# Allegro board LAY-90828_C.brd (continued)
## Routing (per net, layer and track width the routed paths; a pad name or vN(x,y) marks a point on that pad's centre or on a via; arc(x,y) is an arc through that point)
AGND: length 8.9
  TOP w0.203: U1.R6 v2(62.66,24.5)
  BOTTOM w0.381: C109.2 62.31,21.41 62.44,21.54 C31.2 ; C31.2 C29.2 61.29,22.18 61.04,22.43 60.15,22.43 C9.2 ; C31.2 62.82,22.18 63.07,22.43 63.07,24.09 v2(62.66,24.5)
  BOTTOM w0.508: C109.2 R64.2
GND: length 400.2
  TOP w0.102: U1.T16 66.63,23.44 v2(66.63,23.19) ; U1.H5 v2(61.69,27.5) U1.J4 ; U1.J10 v2(63.69,27.5) ; v2(63.69,27.5) U1.J8 ; v2(63.69,27.5) U1.K9 ; v2(63.69,27.5) U1.H9 ; U1.D9 v2(63.18,30) ; v2(99.76,34.1) 99.62,33.97 U6.B2 ; 58.86,28.5 U1.G2 ; U1.J14 66.19,27.97 v2(66.16,28) U1.H13 ; U1.E5 v2(61.69,30.01) 61.7,30 U1.D6 ; U1.P16 67.99,24.2 v2(68.13,24.2) ; U1.P12 65.68,25 v2(65.69,24.99) ; U1.P14 65.7,25 v2(65.69,24.99) ; U1.E13 v2(65.69,30) 65.61,30 65.6,30 U1.D12 ; v2(65.69,24.99) U1.N13 ; U1.P9 v2(63.18,25) ; U6.B10 100.84,31.12 v2(101.03,30.93)
  TOP w0.127: v1(56.32,27.89) 56.96,27.89 57.58,28.5 58.86,28.5 ; v2(27.18,27.31) 27.28,27.31 U8.B9
  TOP w0.203: U1.P6 U1.P7 v2(63.18,25) ; v2(28,24.32) 28,24.59 U8.B13 ; v2(23.11,26.29) 22.71,25.89 U8.M11 U8.M12 U8.N12 22.07,25.38 v2(21.53,24.83) ; U8.B1 27.71,31.14 v2(28,31.44) ; U8.B5 v2(27.21,28.88) ; U8.J13 24.21,24.44 v2(24.32,24.32) ; U41.10 14.74,17.39 v1(14.54,17.59) ; U8.N5 v2(21.54,28.88)
  TOP w0.254: v1(38.34,12.19) 38.34,12.04 38.09,11.79 U4.D3 ; v1(38.34,12.19) U4.C3 ; v1(38.34,12.19) 38.34,12.33 38.09,12.59 U4.B3 ; v2(24.45,31.44) 24.71,31.18 U8.H1 U8.H2 ; v1(21.78,31.31) U8.N1 ; U10.10 86.04,30.26 85.79,30 v1(85.79,29.66)
  TOP w0.381: R185.2 46.67,19.37 v1(46.29,18.99) ; R297.3 v1(9.71,15.31) ; C82.2 v1(10.35,40.71) ; C79.2 v1(20.76,32.19) ; U9.7 v1(9.33,34.74) ; C88.2 v1(107.12,10.23) ; Y3.2 52.68,28.48 v1(52.39,28.77) ; C67.2 v1(32.7,28.26) ; R94.2 38.52,12.01 v1(38.34,12.19) ; R197.1 84.01,29.69 v1(84.53,29.16) ; R111.1 v1(85.15,12.01) ; C46.2 v1(73.47,14.16) ; C53.2 v1(101.36,25.72) 102.04,25.72 102.37,26.05 C50.2 ; R126.2 v1(18.99,35.25) ; v1(98.87,22.04) 98.61,22.04 98.21,21.64 U7.6 ; R91.2 37.65,10.61 v1(37.91,10.86) ; v1(94.93,20.64) U7.8 ; C103.2 C102.2 54.67,19.37 54.29,19.75 v1(54.29,19.88) 53.98,20.19 U11.2 ; C150.2 v1(15.05,12.01) ; R191.2 91.88,31.94 92.28,31.55 v1(92.28,31.07) ; R134.2 v1(24.45,21.02) ; v1(65.1,16.59) 64.71,16.19 R100.1 ; C95.2 67.75,21.79 v1(68.26,22.29) 68.64,21.91 C94.2 ; D9.A v1(11.75,3.75) ; C36.2 v1(11.11,23.69) ; v1(103.57,33.34) 103.31,33.6 C42.2 ; C81.2 v1(32.7,33.85) ; v1(19.24,29.92) C78.2 ; C87.2 v1(6.68,45.72) ; R214.2 v1(10.1,37.91) ; v1(95.95,18.23) 95.95,18.36 96.48,18.89 U7.7 ; R132.2 v1(23.18,21.02) ; v1(45.27,21.91) C108.2 C104.1 ; C47.2 v1(95.95,26.36) ; D11.2 13.52,13.15 v1(13.78,12.89) ; C86.2 v1(6.68,46.87) ; C90.2 v1(105.85,44.52) ; R136.2 17.84,28.77 v1(17.72,28.64) R122.2 ; C97.2 v1(56.32,27.89) ; C45.2 v1(95.06,30.09) ; U5.7 v1(9.08,20.13) ; C43.2 v1(103.57,30.67) ; C30.2 C28.2 75.37,26.86 v1(75.63,26.61) ; Y3.4 54.64,30.16 C96.2 56.08,30.16 v1(56.32,29.91) ; C6.2 v1(16.57,35.25) ; v1(97.6,23.05) 97.6,22.67 97.32,22.39 U7.5 ; C44.2 v1(102.81,28.26) ; v1(16.57,11.62) C105.2 ; R130.2 v1(32.69,27.25) ; D14.3 v1(15.81,11.75) ; C49.2 v1(101.54,37.28) ; C58.1 v1(103.57,32.58) ; v1(100.52,37.28) C51.2 C55.2 ; C48.2 v1(103.57,31.69) ; R150.2 v1(10.48,9.47) ; v1(17.72,27.75) C80.2 ; C154.2 v1(12.64,19.88) ; v1(66.99,16.2) 67.12,16.07 R113.2 C54.2 ; C40.2 v1(10.86,24.58) ; C69.2 v1(21.65,39.95) ; v1(86.04,8.58) 85.79,8.32 R112.1 ; C85.2 v1(7.3,12.26) ; R213.2 v1(10.24,33.6) ; C60.2 v1(84.14,6.8) ; R93.2 v1(12.13,23.69) ; R135.2 v1(32.7,31.56) ; C65.2 v1(32.7,23.31) ; C101.2 v1(47.05,22.93) ; C68.2 v1(32.7,30.55) ; C73.2 v1(17.72,26.23) ; R133.2 v1(32.7,29.28) ; R149.2 v1(3.87,15.18) ; D10.A v1(11.75,5.27) ; C59.2 v1(84.14,12.01)
  TOP w0.508: D3.C v1(55.69,13.4) ; C34.2 v1(77.66,22.04) ; C114.2 v1(92.28,20.91) ; 39.96,43.77 v1(37.92,43.77) ; SW3.2 v1(109.7,2.01) ; C5.2 v1(16.19,37.91) ; 46.67,12.13 v1(46.67,12.13) ; 46.67,12.13 C2.2 ; 46.67,12.13 v1(46.67,12.13) ; 46.67,12.13 C3.2 ; v1(46.67,12.13) U2.2 ; C99.2 v1(88.58,27.12) ; C77.2 v1(22.03,19.24) ; C8.2 102.93,17.97 v1(103.5,17.4) U3.1 ; U11.9 v1(51.75,18.74) ; v1(10.75,48.74) SW1.2 ; R137.2 v1(24.07,35.37) ; C74.2 v1(13.14,23.18) ; C38.2 32.57,12.39 v1(32.57,13.4) C39.2 ; Y1.4 19.03,32.79 v1(19.24,32.58) ; C7.2 v1(101.54,12.64) ; R176.1 v1(91.5,28.39) ; C110.2 v1(28.26,8.83) ; Q1.1 v1(33.59,14.78) ; R122.2 16.95,29.28 16.53,29.7 Y1.2 ; C111.2 v1(29.78,8.83) ; C76.2 v1(21.02,23.69) ; v1(25.08,35.37) C70.2 ; C71.2 v1(26.35,36.14) ; C62.2 v1(93.03,23.56) ; v1(109.81,48.74) SW2.2 ; U12.4 v1(85.17,22.32) ; R86.2 v1(79.06,21.4) ; C64.2 v1(35.88,29.02) C63.2 ; v1(19.49,33.98) 20,33.47 C66.2 ; C32.2 v1(70.17,21.02) ; C107.2 v1(94.68,26.99) ; v1(13.14,24.71) C72.2 ; C1.2 v1(49.21,11.5) ; C75.2 v1(20.51,19.24) ; C83.2 v1(22.8,35.37) ; C113.2 v1(23.18,8.83) ; v1(109.81,6.16) SW3.1 ; C98.2 v1(87.57,27.12) ; SW2.1 v1(109.8,52.89) ; C41.2 v1(33.08,8.58) ; SW1.1 v1(10.87,52.89) ; C115.2 v1(92.79,44.53) ; R204.1 v1(93.79,17.85) ; C106.2 v1(94.68,25.98) ; C4.2 v1(49.21,12.77) ; C112.2 v1(26.73,8.83)
  TOP w0.762: J10.SH2 J10.SH4 J10.SH3 J10.SH1 ; J11.SH1 J11.SH3 J11.SH4 J11.SH2
  GND w0.381: 6.05,33.07 J10.A12 ; J10.A12 5.46,33.67 ; J10.A12 6.65,33.67 ; 1.69,25.14 J11.SH3 ; J11.SH3 1.69,26.57 ; J11.SH3 2.81,25.86 ; J7.9 89.29,6.16 ; J7.9 88.2,7.26 ; J7.9 87.11,6.16 ; J7.9 88.2,5.07 ; 29.53,40.07 JP5.1 ; JP5.1 28.38,41.22 ; JP5.1 29.53,42.36 ; JP5.1 30.67,41.22 ; J7.10 89.29,3.62 ; J7.10 87.11,3.62 ; J7.10 88.2,2.53 ; J7.10 88.2,4.72 ; 36,2.28 J3.12 ; J3.12 34.91,3.37 ; J3.12 37.1,3.37 ; J3.12 36,4.46 ; J17.1 3.85,45.16 ; J17.1 1.64,45.16 ; J17.1 2.75,46.27 ; J17.1 2.75,44.06 ; 14.79,42.99 JP7.1 ; JP7.1 15.94,44.14 ; JP7.1 14.79,45.28 ; JP7.1 13.65,44.14 ; J6.8 96.84,17.19 ; J6.8 97.95,16.07 ; J6.8 96.84,14.95 ; J6.8 95.72,16.07 ; 76.33,12.01 J21.1 ; J21.1 78.99,12.01 ; J21.1 77.66,13 ; J21.1 77.66,11.02 ; J4.3 49.81,5.91 ; J4.3 48.7,4.81 ; J4.3 48.7,7.01 ; J4.3 47.6,5.91 ; J10.SH4 2.81,32.32 ; J10.SH4 1.69,31.61 ; J10.SH4 1.69,33.03 ; 5.3,18.56 J11.B1 4.11,18.56 ; 38.54,2.28 J3.14 ; J3.14 38.54,4.46 ; J3.14 37.45,3.37 ; J3.14 39.64,3.37 ; J11.A1 6.05,25.1 ; J11.A1 5.46,24.51 ; J11.A1 6.65,24.51 ; J16.1 102.77,42.49 ; J16.1 101.66,41.38 ; J16.1 101.66,43.59 ; J16.1 100.56,42.49 ; J11.SH1 5.07,26.57 ; J11.SH1 6.54,25.86 ; J11.SH1 3.61,25.86 ; J11.SH1 5.07,25.14 ; 5.3,39.62 J10.B12 4.11,39.62 ; 13.44,5.15 J13.3 ; J13.3 14.54,4.04 ; J13.3 15.64,5.15 ; J13.3 14.54,6.25 ; J8.2 111.34,44.01 ; J8.2 109.26,44.01 ; J8.2 110.3,42.97 ; J8.2 110.3,45.05 ; J5.8 96.84,40.05 ; J5.8 97.95,38.93 ; J5.8 95.72,38.93 ; J5.8 96.84,37.81 ; 74.81,9.87 J21.2 ; J21.2 74.81,12.54 ; J21.2 75.8,11.21 ; J21.2 73.82,11.21 ; J10.SH1 6.54,40.97 ; J10.SH1 3.61,40.97 ; J10.SH1 5.07,41.68 ; J10.SH1 5.07,40.26 ; 1.69,16.49 J11.SH4 ; J11.SH4 1.69,17.92 ; J11.SH4 2.81,17.21 ; JP6.1 19.75,44.14 ; JP6.1 18.6,42.99 ; JP6.1 17.46,44.14 ; JP6.1 18.6,45.28 ; J9.22 77.67,51.63 ; J9.22 76.64,52.66 ; J9.22 76.64,50.6 ; J9.22 75.61,51.63 ; J10.SH3 1.69,41.68 ; J10.SH3 1.69,40.26 ; J10.SH3 2.81,40.97 ; J11.A12 6.65,18.56 ; J11.A12 6.05,17.96 ; J11.A12 5.46,18.56 ; 5.07,16.49 J11.SH2 ; J11.SH2 5.07,17.92 ; J11.SH2 3.61,17.21 ; J11.SH2 6.54,17.21 ; J2.14 21.78,52.72 ; J2.14 21.78,50.54 ; J2.14 20.69,51.63 ; J2.14 22.87,51.63 ; J10.SH2 6.54,32.32 ; J10.SH2 5.07,31.61 ; J10.SH2 3.61,32.32 ; J10.SH2 5.07,33.03 ; 5.46,39.62 J10.A1 ; J10.A1 6.65,39.62 ; J10.A1 6.05,40.22 ; 4.11,24.51 J11.B12 5.3,24.51 ; 5.3,33.67 J10.B1 4.11,33.67 ; 3.61,9.08 J12.5 4.38,7.9 ; 23.79,14.29 J19.2 ; J19.2 24.82,13.26 ; J19.2 25.85,14.29 ; J19.2 24.82,15.32
  POWER w0.381: 89.29,6.16 J7.9 88.2,5.07 ; 3.61,40.97 J10.SH1 ; J10.SH1 5.07,41.68 ; J10.SH1 5.07,40.26 ; J10.SH1 6.54,40.97 ; 4.11,39.62 J10.B12 5.3,39.62 ; J10.A1 6.65,39.62 ; J10.A1 6.05,40.22 ; J10.A1 5.46,39.62 ; 5.46,18.56 J11.A12 ; J11.A12 6.65,18.56 ; J11.A12 6.05,17.96 ; J10.SH3 1.69,41.68 ; J10.SH3 2.81,40.97 ; J10.SH3 1.69,40.26 ; J17.1 2.75,46.27 ; J17.1 2.75,44.06 ; J17.1 3.85,45.16 ; J17.1 1.64,45.16 ; J11.A1 6.65,24.51 ; J11.A1 6.05,25.1 ; J11.A1 5.46,24.51 ; 5.07,31.61 J10.SH2 ; J10.SH2 3.61,32.32 ; J10.SH2 5.07,33.03 ; J10.SH2 6.54,32.32 ; 5.3,33.67 J10.B1 4.11,33.67 ; J10.SH4 2.81,32.32 ; J10.SH4 1.69,33.03 ; J10.SH4 1.69,31.61 ; J2.14 22.87,51.63 ; J2.14 21.78,50.54 ; J2.14 21.78,52.72 ; J2.14 20.69,51.63 ; J7.10 88.2,4.72 ; J7.10 89.29,3.62 ; J7.10 88.2,2.53 ; 5.07,25.14 J11.SH1 ; J11.SH1 3.61,25.86 ; J11.SH1 6.54,25.86 ; J11.SH1 5.07,26.57 ; J11.SH4 1.69,17.92 ; J11.SH4 2.81,17.21 ; J11.SH4 1.69,16.49 ; 1.69,25.14 J11.SH3 ; J11.SH3 1.69,26.57 ; J11.SH3 2.81,25.86 ; 6.05,33.07 J10.A12 ; J10.A12 5.46,33.67 ; J10.A12 6.65,33.67 ; 5.3,18.56 J11.B1 4.11,18.56 ; 5.07,16.49 J11.SH2 ; J11.SH2 3.61,17.21 ; J11.SH2 5.07,17.92 ; J11.SH2 6.54,17.21 ; 4.11,24.51 J11.B12 5.3,24.51
  BOTTOM w0.254: C19.2 66.99,28.64 66.35,28 v2(66.16,28)
  BOTTOM w0.381: C26.2 C25.2 C27.2 62.29,31.31 61.69,30.71 v2(61.69,30.01) 61.21,29.53 C21.2 ; C19.2 C15.2 68.28,28.62 C18.2 ; C11.2 C35.2 61.57,27.38 v2(61.69,27.5) ; C20.2 v2(68.13,24.2) ; v2(66.63,23.19) 66.12,22.68 65.86,22.68 65.86,22.3 66.25,21.92 C24.2
  BOTTOM w0.508: C21.2 C23.2 C22.2 ; v1(56.32,27.89) 57.97,27.89 C12.2 C10.2 ; v1(63.13,17.54) R64.1 ; v1(71.06,32.07) 71.06,31.94 70.67,31.56 C13.2 C17.2 C14.2 C16.2
P5V0: length 167.7
  TOP w0.254: U4.B2 U4.B1 36.2,12.59 v1(36,12.39) 36.2,12.19 U4.C1
  TOP w0.381: 11.38,29.42 D1.C 10.11,30.23 ; D4.C 13.56,29.8 ; D4.C 12.75,31.07 ; D4.C 11.94,29.8 ; C6.1 14.79,35.83 ; C6.1 14.21,35.25 ; C6.1 14.79,34.66 ; 44,9.59 41.21,9.59 40.58,10.23 40.58,13.4 40.81,13.63 U2.1 ; TP2.1 13.65,33.86 ; TP2.1 13.65,32.31 ; TP2.1 12.88,33.09 ; TP2.1 14.43,33.09 ; C7.1 103.19,11.75 106.38,14.94 106.38,34.5 102.44,38.43 101.04,38.43 96.34,43.13 v1(96.34,44.53) ; 14.67,36.06 C5.1 ; C5.1 14.67,37.74 ; C5.1 13.96,36.9 ; v1(57.09,18.61) R179.1 ; 13.21,36.75 D2.C 12.39,35.48
  TOP w0.508: R182.2 20.26,13.28 v1(20.51,13.53) ; v1(62.17,15.56) 62.17,15.31 v1(57.34,10.48) 56.2,9.34 48.96,9.34 ; C39.1 C38.1 35.11,12.01 35.5,12.39 v1(36,12.39) ; v1(102.55,10.87) C7.1 U3.3 ; v1(94.31,44.53) R207.1 ; J3.10 33.46,2.35 32.83,1.72 22.92,1.72 21.78,2.86 v1(21.78,11.62)
  BOTTOM w0.508: v1(57.34,10.48) 57.34,14.42 57.09,14.67 v1(57.09,18.61) ; v1(62.17,15.56) 73.62,15.56 75.77,13.41 81.1,13.41 83.26,11.25 86.95,11.25 88.47,9.73 93.55,9.73 94.68,10.86 102.54,10.86 v1(102.55,10.87) ; v1(94.31,44.53) v1(96.34,44.53)
  vias: v1(14.16,30.42) v1(14.16,29.4) v1(20.51,14.42) v1(46.04,9.21) v1(47.18,9.21)
P5V_HDR_IN: length 3.3
  TOP w0.762: J19.3 22.28,13.16 23.18,12.26 C113.1
  vias: v1(13.78,27.63) v1(13.78,26.61)
P5V_MCU_LINK_USB: length 13.7
  TOP w0.381: v1(15.56,33.85) 15.56,29.02 R121.1
  BOTTOM w0.381: TP13.1 12.24,39.7 v1(12.38,39.56) 12.38,37.02 v1(15.56,33.85)
P5V_USB_HS: length 5.7
  TOP w0.381: 9.26,26.86 C40.1 ; C40.1 10.1,27.58 ; C40.1 10.93,26.86 ; L3.2 8.44,27.71 ; L3.2 7.82,26.95 ; L3.2 9.07,26.95
  BOTTOM w0.381: TP14.1 9.47,28.26 v1(8.19,28.26)
VBAT_DCDC/VBAT_PMU: length 10
  TOP w0.203: U8.N13 22.21,24.28 v1(22.41,24.07) 22.71,24.37 U8.M13
  TOP w0.381: v1(22.41,24.07) 22.41,23.82 22.03,23.44 C76.1
  TOP w0.508: L13.2 C75.1 C77.1 C76.1
  BOTTOM w0.381: TP17.1 22.41,23.46 v1(22.41,24.07)
VDD_1V8: length 19.9
  TOP w0.102: U6.B6 100.56,32.12 v2(100.9,32.45) 101.09,32.64
  TOP w0.127: 101.09,32.64 101.28,32.83 101.28,33.09 C42.1
  TOP w0.508: U3.2 101.6,17.34 101.66,17.4 C8.1 101.66,19.12 102.04,19.5 J20.1
  BOTTOM w0.508: v2(100.9,32.45) 102.04,31.31 J20.1
VDD_ACCL: length 24.7
  TOP w0.254: U10.1 87.91,30.26 87.57,29.91 C98.1
  TOP w0.381: v1(86.68,29.02) C98.1 ; R175.2 v1(92.26,30.17) ; R174.1 R173.1 83.63,31.06 v1(83.26,30.69)
  TOP w0.508: R171.2 C99.1 C98.1 ; R202.1 R175.2
  BOTTOM w0.381: v1(92.26,30.17) R175.2 90.36,29.02 v1(86.68,29.02) ; v1(83.26,30.69) 85.8,30.69 86.68,29.81 v1(86.68,29.02) ; TP23.1 85.93,28.28 v1(86.68,29.02)
VDD_AUDIO: length 28.4
  TOP w0.102: 100.65,29.53 100.06,30.12 U6.B14
  TOP w0.152: U6.D10 98.04,31.12 97.71,30.79 v1(97.61,30.79)
  TOP w0.254: U7.4 96.54,21.57 95.57,22.55 95.06,22.55
  TOP w0.381: v1(97.61,30.79) C45.1 R95.2 ; 100.65,29.53 100.65,29.4 v2(100.9,29.15) C44.1
  TOP w0.508: 95.06,22.55 v1(94.55,22.55) C62.1 R203.1
  BOTTOM w0.381: TP18.1 94.55,22.03 v1(94.55,22.55)
  BOTTOM w0.508: v1(94.55,22.55) 94.55,23.69 92.9,25.34 92.9,29.4 94.3,30.8 97.6,30.8 v1(97.61,30.79) 97.99,30.79 99.63,29.15 v2(100.9,29.15)
VDD_BOARD: length 114.4
  TOP w0.203: U41.12 13.94,17.05 13.78,17.21 13.02,17.21 v1(12.89,17.34) 12.64,17.59 C154.1
  TOP w0.381: R188.1 81.09,22.55 80.71,22.93 80.71,24.71 81.09,25.09 R187.1 ; R161.1 v1(6.6,44.83) ; R166.1 101.93,10.24 v1(102.06,10.11) ; R95.1 v1(95.06,29.08) ; R163.1 v1(9.59,46.42) ; R162.1 v1(106.11,10.23) ; R297.1 v1(10.86,16.32) ; R158.1 v1(32.7,32.45) ; R278.1 v1(13.65,19.88) ; C85.1 v1(7.3,15.69) ; R125.1 v1(18.99,36.77) ; v1(48.83,30.42) 48.58,30.42 48.2,30.04 R44.1 R43.1 ; R119.1 v1(26.5,42.97) ; v1(18.35,15.94) 18.22,15.94 R257.1 ; R146.1 v1(4.89,15.18) ; R127.1 v1(32.32,36.9) ; R120.1 v1(24.97,43.01) ; v1(14.92,19.75) 15.18,19.5 R265.1 ; R147.1 v1(5.9,15.18) ; R180.2 v1(47.05,22.04) ; R294.1 18.35,14.29 v1(18.48,14.42) ; R298.1 v1(47.43,24.83) ; R87.1 v1(40.07,15.69) ; R90.1 v1(36.25,16.57) ; R145.1 v1(2.86,15.31) ; R157.1 v1(32.7,24.58) ; R299.1 v1(47.43,25.72) ; R144.1 v1(1.84,15.31) ; R118.1 v1(23.45,43.01) ; R164.1 v1(106.74,44.52)
  TOP w0.508: R172.2 v1(32.84,44.91) ; R6.1 v1(27.89,45.16) ; U12.8 92.14,26.1 92.26,25.98 C106.1 C107.1 92.14,26.99 v1(91.88,27.25) ; R7.1 v1(27.89,43.77) ; R206.1 v1(87.84,20.91) ; R188.1 v1(81.47,21.66) ; L12.1 v1(29.02,35.33) ; R186.1 v1(94.68,25.09) ; L13.1 v1(16.19,21.66) ; R171.1 v1(89.6,27.12)
  POWER w0.381: J7.12 86.75,3.62 ; J7.12 84.57,3.62 ; J7.12 85.66,4.72 ; J7.12 85.66,2.53 ; J4.1 47.27,5.91 ; J4.1 45.06,5.91 ; J4.1 46.16,7.01 ; J4.1 46.16,4.81 ; J3.8 30.92,4.46 ; J3.8 30.92,2.28 ; J3.8 29.83,3.37 ; J3.8 32.02,3.37 ; J7.11 86.75,6.16 ; J7.11 84.57,6.16 ; J7.11 85.66,5.07 ; J7.11 85.66,7.26 ; 41.72,25.47 JP1.1 40.57,26.61 ; J8.1 113.88,44.01 ; J8.1 112.84,45.05 ; J8.1 111.8,44.01 ; J8.1 112.84,42.97 ; J3.4 25.84,4.46 ; J3.4 24.75,3.37 ; J3.4 25.84,2.28 ; J3.4 26.94,3.37 ; J9.21 76.64,50.12 ; J9.21 77.67,49.09 ; J9.21 75.61,49.09 ; J9.21 76.64,48.06
  BOTTOM w0.381: v1(36.25,16.57) 37.53,17.85 44.13,17.85 45.91,19.63 47.43,19.63 48.7,20.9 48.7,30.29 v1(48.83,30.42)
  BOTTOM w0.508: JP1.1 41.72,23.84 TP24.1 42.37,23.19 45.39,23.19 46.54,22.04 v1(47.05,22.04) 47.43,22.04 47.81,22.42 47.81,24.45 v1(47.43,24.83) v1(47.43,25.72)
  vias: v1(34.86,31.82) v1(34.86,30.93)
VDD_CORE: length 14.9
  TOP w0.102: U1.K10 64.67,27 v2(64.69,26.98)
  TOP w0.254: U1.L11 v2(64.69,26.98)
  TOP w0.508: v1(76.14,24.45) 76.31,24.45 76.77,23.99 R83.1 R84.2
  BOTTOM w0.381: C18.1 68.3,27.67 C15.1 C19.1
  BOTTOM w0.508: C18.1 70,27.67 v1(70.29,27.37) 70.68,27.37 71.45,28.15 TP19.1 72.47,27.51 73.99,27.51 74.75,26.75 74.75,25.83 v1(76.14,24.45)
VDD_DCDC: length 14.5
  TOP w0.102: U1.R15 67.16,24.5 v2(67.19,24.47)
  TOP w0.508: R80.1 74.74,19.63 R79.2 73.98,20.26 v1(73.47,20.77) 73.21,21.02 C32.1
  BOTTOM w0.381: TP25.1 73.47,20.67 v1(73.47,20.77) 73.47,21.28 69.91,24.83 67.55,24.83 v2(67.19,24.47)
VDD_LDO_CORE_IN: length 30.1
  TOP w0.102: U1.K6 62.19,27.4 v2(62.29,27.5)
  TOP w0.508: v1(78.68,22.42) 79.31,22.42 79.69,22.8 R84.1 R85.2
  POWER w0.381: v2(62.29,27.5) 62.99,27.5 63.48,28 63.49,28 64.18,28.69 64.18,28.7 64.2,28.71 64.2,29.28 65.72,30.8 71.44,30.8 71.82,30.42 71.82,29.28 75.63,25.47 76.52,25.47 78.68,23.31 v1(78.68,22.42)
  BOTTOM w0.254: C35.1 61.41,26.37 62.29,27.25 v2(62.29,27.5)
  BOTTOM w0.381: v1(78.68,22.42) 78.95,22.69 TP26.1
VDD_LDO_SYS_IN: length 13.7
  TOP w0.102: U1.P15 66.99,25.3 68.52,25.3
  TOP w0.127: v1(72.2,25.47) 72.03,25.3 68.52,25.3
  TOP w0.381: v1(72.2,25.47) 72.58,25.85 R82.1 C30.1 73.85,25.47 74.23,25.09 75.25,25.09 75.63,25.47 76.39,25.47 76.64,25.21 R78.2
  BOTTOM w0.381: v1(72.2,25.47) 73.71,23.95 TP27.1
VDD_MCU: length 21.6
  TOP w0.102: U1.H6 62.55,28 62.58,28.03 v2(62.69,28.03) U1.G7 62.71,28.52 v2(63.18,28.52) 63.19,28.51 U1.H8
  TOP w0.508: R76.1 v1(72.58,18.23) 72.71,18.1 R79.1 ; R85.1 78.17,25.98 v1(77.91,26.23) 77.41,26.74 R78.1
  POWER w0.381: JP3.1 45.4,34.23 ; JP3.1 44.26,35.37 ; JP3.1 43.11,34.23
  BOTTOM w0.381: 64.98,22.68 64.98,22.3 65.23,22.05 C24.1 v1(65.23,20.65) ; R74.1 55.31,28.29 TP28.1 ; C27.1 C25.1 C26.1
  BOTTOM w0.508: v1(71.94,32.2) R75.1 ; R77.1 60.26,33.6 v1(60.58,33.91) 60.77,33.91 61.28,33.41 C26.1 ; v1(53.78,26.23) 54.29,26.74 R74.1
VDD_P2: length 13.5
  TOP w0.102: U1.K8 62.7,27 v2(62.69,26.99) U1.L7
  POWER w0.381: 60.01,28.26 61.28,26.99 v2(62.69,26.99)
  POWER w0.508: 60.01,28.26 58.74,29.53 v1(57.72,29.53)
  BOTTOM w0.381: v1(57.72,29.53) 57.72,30.92 TP29.1
  BOTTOM w0.508: v1(57.72,29.53) C21.1 C23.1 C22.1 58.74,32.07 R77.2
VDD_P3: length 9.5
  TOP w0.102: U1.H10 v2(64.7,28) ; v2(64.7,28) U1.H12 ; v2(64.7,28) 64.69,28.01 U1.G11
  BOTTOM w0.381: TP30.1 73.24,29.79 R75.2
  BOTTOM w0.508: R75.2 71.56,29.79 71.18,30.17 C13.1 70.67,29.79 v1(70.29,29.4) 69.79,29.91 C17.1 C14.1 C16.1
VDD_P4: length 8.7
  TOP w0.102: U1.P4 U1.N5
  TOP w0.254: U1.N5 v2(61.69,25.99)
  BOTTOM w0.381: TP31.1 58.12,26.11 57.99,26.24 C12.1 ; C12.1 57.61,26.88 57.47,26.74 R74.2 ; C12.1 C10.1 59.51,26.37 C11.1 60.02,26.11 60.4,25.73 61.44,25.73 v2(61.69,25.99)
VDD_SYS: length 9.6
  TOP w0.102: U1.N14 67.95,25.5 68.04,25.59 68.52,25.59
  TOP w0.127: 68.52,25.59 70.4,25.59 70.4,25.59 71.31,25.59 71.56,25.85
  TOP w0.381: 71.56,25.85 v1(72.2,26.48) 72.58,26.86 R82.2 C28.1
  BOTTOM w0.381: v1(72.2,26.48) 72.44,26.24 TP20.1
VDD_USB: length 2.3
  TOP w0.102: U1.R12 v2(64.72,24.5)
  BOTTOM w0.381: v2(64.72,24.5) 64.98,24.24 R24.2 C33.1
VDD_VBAT: length 8.1
  TOP w0.102: v2(68.13,23.31) 68.13,23.55 U1.T17
  TOP w0.508: v1(70.42,20.13) 70.42,20.01 R76.2
  BOTTOM w0.381: v2(68.13,23.31) 68.26,23.18 C20.1 ; TP32.1 70.56,19.99 v1(70.42,20.13)
  BOTTOM w0.508: v1(70.42,20.13) 69.91,20.13 69.4,20.64 69.4,22.67 C20.1
VDDA_MCU: length 70.1
  TOP w0.203: U1.R5 v2(61.69,23.94)
  TOP w0.508: J2.16 20.51,50.36 20.51,47.95 21.77,46.69 29.16,46.69 31.96,43.89 v1(34.24,43.89)
  POWER w0.508: v1(58.88,21.67) 59.56,20.99 59.56,20.27 59.05,19.76 56.44,19.76 53.14,23.07 52.15,23.07 49.61,25.61 49.61,26.37 45.56,30.42 40.7,30.42 39.94,31.18 39.94,32.71 34.86,37.79 34.86,43.25 34.24,43.87 v1(34.24,43.89)
  BOTTOM w0.381: v1(58.88,21.67) 58.96,21.75 58.96,22.9 59.64,23.57 C9.1 60.4,23.95 R23.1 61.68,23.95 v2(61.69,23.94) 61.8,23.94 62.44,23.31 C31.1
  BOTTOM w0.508: C109.1 60.78,21.16 60.28,21.67 L1.2 v1(58.88,21.67)
ANA_7/VREFO: length 63.5
  TOP w0.102: U1.U4 60.78,23.1 v2(60.78,23.07)
  POWER w0.381: v2(60.78,23.07) 60.53,22.81 58.5,22.81 56.59,24.72 52.91,24.72 51.39,26.24 51.39,26.98 45.4,32.96 40.83,32.96 35.75,38.04 35.75,43.76 32.57,46.93 15.18,46.93 14.16,47.95 J2.19
  BOTTOM w0.381: v2(60.78,23.07) 60.91,23.19 C29.1
AUX_L: length 33.6
  TOP w0.102: U6.C13 98.68,30.36 98.36,30.04
  TOP w0.254: v1(96.2,23.31) 95.95,23.56 95.95,25.12 97.85,27.02 97.85,28.39 98.11,28.64 98.11,29.79 98.36,30.04 ; v1(97.6,12.77) 97.09,12.26 88.71,12.26 88.2,11.75 88.2,9.97 87.57,9.34 C57.2
  BOTTOM w0.254: v1(96.2,23.31) 96.2,22.55 97.47,21.28 97.47,17.85 98.11,17.21 98.11,13.02 97.85,12.77 v1(97.6,12.77)
AUX_R: length 33.2
  TOP w0.102: 98.6,29.77 U6.D14
  TOP w0.254: C56.2 87.57,10.23 87.82,10.48 87.82,12.01 88.58,12.77 v1(96.84,12.77) ; v1(96.96,23.31) 96.46,23.82 96.46,25.09 98.36,26.99 98.36,28.26 98.49,28.39 98.49,29.66 98.6,29.77
  BOTTOM w0.254: v1(96.96,23.31) 96.96,22.67 97.85,21.78 97.85,18.1 98.61,17.34 98.61,12.77 98.11,12.26 97.34,12.26 v1(96.84,12.77)
CAMERA_HSYNC: length 34.9
  TOP w0.127: v1(65.86,35.51) 65.36,36.02 65.36,38.05 65.74,38.43 65.74,46.56 67.77,48.59 v1(67.77,52.53)
  BOTTOM w0.127: J9.18 80.44,52.91 68.15,52.91 v1(67.77,52.53) ; v1(65.86,35.51) 66.88,34.5 SJ5.2
CAMERA_PCLK: length 22.7
  TOP w0.127: J9.15 84.26,42.01 v1(84.66,41.61)
  BOTTOM w0.127: SJ4.2 70.69,42.5 70.94,42.75 72.85,42.75 73.61,41.99 84.28,41.99 v1(84.66,41.61)
CAN1_H: length 46.5
  TOP w0.127: D14.2 16.76,7.37 15.94,6.54 15.94,3.75 J13.2 ; D14.2 18.85,8.24 R184.1 ; D14.2 16.76,9.4 v1(16.83,9.47) ; R183.1 v1(47.05,20.26) C104.2
  BOTTOM w0.127: v1(16.83,9.47) 17.21,9.85 18.22,9.85 18.73,10.35 28.26,10.35 30.54,12.64 30.54,13.4 36,18.86 36.77,18.86 38.16,20.26 v1(47.05,20.26)
CAN1_H_R: length 1.5
  TOP w0.127: R183.2 48.9,20.19 U11.7
CAN1_L: length 48.9
  TOP w0.127: D14.1 14.85,8.25 R189.2 ; D14.1 v1(14.86,9.47) ; D14.1 14.86,7.24 15.68,6.42 15.68,3.75 J13.4 ; R190.1 v1(47.05,21.15) C108.1
  BOTTOM w0.127: v1(14.86,9.47) 15.49,10.1 17.97,10.1 18.48,10.61 28.13,10.61 30.29,12.77 30.29,13.53 36,19.24 36.51,19.24 38.42,21.15 v1(47.05,21.15)
CAN1_L_R: length 1.6
  TOP w0.127: R190.2 49.14,20.84 U11.6
CAN_VIO_3V3: length 11.4
  TOP w0.381: v1(49.72,22.93) C101.1 R180.1 49.17,22.04 49.72,21.49 U11.5 ; R181.1 v1(46.93,18.48)
  BOTTOM w0.381: TP22.1 49.74,22.94 v1(49.72,22.93) 49.72,20.51 R181.1 v1(46.93,18.48)
DBGIF_DETECT: length 40.6
  TOP w0.127: v1(9.84,14.16) 9.33,13.66 9.33,10.86 10.22,9.97 10.98,9.97 11.37,9.59 11.37,8.58 10.98,8.2 R148.1 ; v1(27.11,23.44) 26.86,23.69 26.86,25.34 26.73,25.47 26.73,26.36 U8.E9
  BOTTOM w0.127: v1(9.84,14.16) 10.73,15.05 15.94,15.05 18.1,12.89 25.08,12.89 25.84,13.66 25.84,22.17 v1(27.11,23.44)
DBGIF_ISP0_CTRL: length 9.6
  TOP w0.102: U8.C13 27.21,24.1 27.24,24.07
  TOP w0.127: R141.1 34.23,21.02 32.96,22.29 30.54,22.29 29.65,23.18 28.13,23.18 27.24,24.07
DBGIF_RESET: length 11.8
  TOP w0.127: U8.E6 26.61,28.78 26.61,29.28 26.86,29.53 26.86,31.06 27.75,31.94 28.13,31.94 30.92,34.74 R140.1
DBGIF_TCK_SWCLK: length 8.6
  TOP w0.127: U8.L12 23.58,25.01 23.58,23.92 23.81,23.69 23.81,20.77 24.57,20.01 JP8.1
DBGIF_TDI: length 12.2
  TOP w0.127: U8.F5 26.55,29.72 26.55,31.26 27.62,32.33 28,32.33 31.3,35.63 R143.1
DBGIF_TDO_SWO: length 13.8
  TOP w0.127: v1(29.78,29.02) 30.67,29.91 32.83,29.91 33.21,30.29 33.21,32.33 33.72,32.83 R142.1 ; v2(25.71,27.88) U8.F8
  BOTTOM w0.127: v2(25.71,27.88) 26.72,26.86 28.76,26.86 29.65,27.75 29.65,28.9 v1(29.78,29.02)
DBGIF_TMS_SWDIO: length 6.9
  TOP w0.127: R139.1 33.72,26.23 28.06,26.23 U8.B11
DBGIF_VREF: length 11.4
  TOP w0.254: C83.1 22.8,31.82 23.21,31.4 U8.L1
  TOP w0.508: C83.1 22.29,33.6 v1(21.91,33.98) 21.53,34.36 R126.1 R125.2
  BOTTOM w0.381: v1(21.91,33.98) 20.78,35.1 TP10.1
DCDC_LX: length 7.4
  TOP w0.254: U1.P17 68.22,25 68.52,24.71
  TOP w0.508: R81.2 74.87,20.51 73.21,22.17 71.44,22.17 71.06,22.54 71.06,23.82
  vias: v1(70.04,23.44)
DCDC_VDD_CORE: length 2.1
  BOTTOM w0.381: v1(74.37,22.94) 75.52,21.8 TP11.1
HP_L: length 4.3
  TOP w0.102: U6.A3 100.39,33.29 100.39,34.36 100.46,34.42
  TOP w0.127: L7.2 C49.1 101.41,35.37 100.46,34.42
HP_R: length 58.6
  TOP w0.102: U6.A5 100.3,32.36 101.03,33.09 101.03,33.72 101.08,33.78
  TOP w0.254: 101.08,33.78 101.54,34.23 103.69,34.23 104.58,33.34 104.58,24.58 103.57,23.56 100.9,23.56 100.14,22.8 100.14,18.74 v1(100.27,18.61) 100.39,18.48 100.39,15.05 99,13.66 76.39,13.66 76.26,13.53 71.94,13.53 71.69,13.78 C46.1 L6.2
HP_S: length 66.3
  TOP w0.102: 100.76,33.83 100.76,33.2 100.17,32.61 U6.B4
  TOP w0.127: 100.76,34.09 100.76,33.83
  TOP w0.254: v1(99.44,18.93) 98.61,18.1 98.61,15.31 98.11,14.8 75.53,14.8 74.51,15.82 72.2,15.82 71.31,16.7 65.98,16.7 65.72,16.45 R100.2 R98.1 R97.2 ; 100.76,34.09 101.41,34.74 103.95,34.74 105.09,33.6 105.09,24.2 103.82,22.93 v1(101.15,22.93)
  BOTTOM w0.254: v1(99.44,18.93) 99.44,20.96 101.15,22.67 v1(101.15,22.93)
HS_1: length 3.2
  TOP w0.254: J14.1 66.36,13.28 66.74,13.66 R102.2 R98.2
HS_2: length 3.9
  TOP w0.254: J14.2 63.51,13.09 63.69,13.28 R101.1 R97.1
HS_USB1_DM: length 23.9
  TOP w0.127: v1(10.86,35.37) 10.72,35.51 10.09,35.51
  TOP w0.13: J10.B7 5.55,36.22 J10.A7 ; U8.N6 20.64,28.38 v1(20.51,28.52)
  BOTTOM w0.13: v1(20.51,28.52) 20.51,28.8 20.15,29.16 15.95,29.16 15.06,30.05 15.06,32.34 11.78,35.62 11.1,35.62 v1(10.86,35.37) 10.61,35.62 9.5,35.62 8.61,36.51 6.35,36.51 J10.A7
HS_USB1_DP: length 25.3
  TOP w0.127: v1(10.86,36.14) 10.73,36.01 10.09,36.01
  TOP w0.13: U8.M6 v2(23.2,28.38)
  BOTTOM w0.13: v2(23.2,28.38) 21.31,28.38 20.26,29.43 16.07,29.43 15.33,30.16 15.33,32.45 11.89,35.89 11.1,35.89 v1(10.86,36.14) 10.61,35.89 9.61,35.89 8.72,36.78 6.35,36.78 J10.A6 5.55,37.07 J10.B6
HW_VER_0: length 5.4
  TOP w0.127: R130.1 30.16,27.25 29.45,26.54 27.05,26.54 U8.E8
HW_VER_1: length 3.5
  TOP w0.127: U8.A8 28.9,27.38 30.8,29.28 R133.1
HW_VER_2: length 5.5
  TOP w0.102: U8.F9 25.31,26.48 24.7,26.48 23.81,25.59 23.81,24.2 23.94,24.07
  TOP w0.127: 23.94,24.07 24.45,23.56 R134.1
HW_VER_3: length 5.5
  TOP w0.127: R135.1 30.16,31.56 29.53,30.93 29.53,30.55 28.51,29.53 27.57,29.53 27.36,29.74 27.36,30.02 27.37,30.02 27.37,30.04 U8.B2
HW_VER_4: length 3.6
  TOP w0.127: U8.M5 22.34,29.25 20.48,29.25 20,28.77 R136.1
HW_VER_5: length 5.2
  TOP w0.127: U8.H5 24.71,29.27 23.81,30.17 23.81,31.56 24.07,31.82 R137.1
HW_VER_6: length 18.4
  TOP w0.102: U8.H9 24.71,26.87 24.32,26.48 24.07,26.48 23.81,26.74 23.81,28.39 23.05,29.15 v2(23.05,29.4)
  BOTTOM w0.102: 23.05,31.82 v2(23.05,29.4)
  BOTTOM w0.127: JP6.2 19.01,41.6 21.8,38.81 21.8,35.23 23.05,33.98 23.05,31.82
HW_VER_7: length 15.1
  TOP w0.102: U8.N2 21.82,30.38 21.4,30.8
  TOP w0.127: 21.4,30.8 21.27,30.93 21.27,32.45 20.89,32.83 19.87,32.83 17.08,35.63 17.08,37.91 14.79,40.2 JP7.2
HW_VER_8: length 2.1
  TOP w0.127: R132.1 23.21,22.83 U8.L13
JTAG_VREF: length 5.5
  TOP w0.127: J12.1 1.08,9.08 0.95,9.21 0.95,11.88 1.84,12.77 R144.2
LDO_3V3: length 16.1
  TOP w0.508: J15.1 52.78,11.51 53.03,11.75 R70.1
  TOP w0.635: J15.1 51.13,12.65 50.62,13.16 R8.2
  POWER w0.381: J15.1 51.13,12.61 ; J15.1 51.13,10.4 ; J15.1 52.24,11.51 ; J15.1 50.03,11.51 ; JP1.2 44.26,27.75 ; JP1.2 44.26,25.47 ; JP1.2 45.4,26.61 ; 45.4,29.15 JP2.2 44.26,28.01
LED_USB_COMM: length 14.1
  TOP w0.127: v2(26.22,26.1) 26.22,25.9 U8.F12 ; D6.C v1(23.45,37.17)
  BOTTOM w0.102: v2(26.22,26.1) 26.22,26.61 24.95,27.88 24.95,31.69 24.83,31.82
  BOTTOM w0.127: v1(23.45,37.17) 23.45,33.2 24.83,31.82
LED_VCOM_ACT: length 11.9
  TOP w0.127: v2(26.86,28.26) 26.98,28.38 U8.B6 ; D8.C v1(24.97,37.17)
  BOTTOM w0.102: 25.21,31.82 25.21,29.91 v2(26.86,28.26)
  BOTTOM w0.127: 25.21,31.82 25.21,31.94 24.57,32.58 24.57,36.77 v1(24.97,37.17)
MCU_HS_USB1_DM: length 8.4
  TOP w0.13: 9.84,20.9 10.47,20.9 v1(10.6,20.77) 10.62,20.75 L4.1
  BOTTOM w0.13: v1(10.6,20.77) 10.2,20.77 9.96,21.02 9.11,21.02 8.73,21.4 6.35,21.4 J11.A7 5.55,21.11 J11.B7
MCU_HS_USB1_DP: length 8.4
  TOP w0.13: 9.84,21.4 10.48,21.4 v1(10.6,21.53) 10.62,21.55 L4.4 ; J11.B6 5.55,21.96 J11.A6
  BOTTOM w0.13: v1(10.6,21.53) 10.2,21.53 9.96,21.28 9.23,21.28 8.85,21.67 6.35,21.67 J11.A6
MCU_LINK_3V3: length 46.2
  TOP w0.203: C67.1 30.54,28.26 v1(30.22,27.94) 29.16,26.88 U8.A9 ; C81.1 v1(30.3,33.33) 28.64,31.67 28.64,30.17 28.35,29.88 U8.A3 ; U8.A5 28.49,28.88 v1(30.16,30.55) C68.1 ; U8.N7 v1(21.14,27.88) ; U8.A13 28.76,24.32 29.78,24.32 v1(30.16,23.94) 30.8,23.31 C65.1
  TOP w0.254: U8.M1 22.71,31.14 22.29,31.56 22.29,32.45 v1(21.91,32.83) C66.1
  TOP w0.381: v1(21.14,27.88) 21.02,27.75 C80.1 ; R116.1 v1(18.73,38.93)
  POWER w0.508: v1(30.3,33.33) 29.9,33.72 22.8,33.72 v1(21.91,32.83) 21.91,32.45 22.67,31.69 22.67,30.42 22.29,30.04 22.29,28.39 21.78,27.88 v1(21.14,27.88)
  BOTTOM w0.381: TP12.1 17.59,38.93 v1(18.73,38.93)
  BOTTOM w0.508: v1(18.73,38.93) 18.73,38.32 20.02,37.04 20.02,34.72 v1(21.91,32.83)
  vias: v1(33.46,28.52) v1(33.46,27.63)
MCU_LINK_I2C0_SCL: length 7.8
  TOP w0.127: U8.A12 28.76,24.83 29.91,24.83 30.16,24.58 R157.2 30.92,24.1 31.2,23.82 33.34,23.82 v1(33.72,23.44) 34.1,23.05 R159.2
MCU_LINK_I2C0_SDA: length 13.1
  TOP w0.127: R160.2 33.72,33.85 32.96,33.09 31.18,33.09 30.92,32.83 R158.2 30.29,32.45 v1(29.4,31.56) ; U8.E7 26.45,27.88 26.66,27.68 v2(26.66,27.68)
  BOTTOM w0.127: v1(29.4,31.56) 29.27,31.44 29.27,27.88 29.02,27.63 28.13,27.63 28,27.75 26.74,27.75 v2(26.66,27.68)
MCU_LINK_N_16MHZ: length 5.2
  TOP w0.127: U8.M3 22.36,29.53 21.65,29.53 21.4,29.79 20.51,30.67 C78.1 19.24,30.67 19.16,30.59 Y1.3
MCU_LINK_P_16MHZ: length 7.6
  TOP w0.127: U8.N3 21.81,29.88 20.64,31.06 20.64,31.31 20.5,31.44 C79.1 19.49,31.44 19.24,31.69 16.7,31.69 16.53,31.86 Y1.1
MCU_LINK_RST: length 10.7
  TOP w0.102: 23.43,31.82 23.56,31.69 23.56,29.02 24.2,28.38 U8.J6
  TOP w0.127: R117.2 v1(22.29,37.41) 23.43,36.26 23.43,31.82
MCU_LINK_RX: length 58.4
  TOP w0.127: R55.1 47.94,27.75 47.43,28.26 47.43,30.29 48.34,31.2 48.34,31.57 49.86,33.1 v1(49.86,33.23) ; U8.E12 26.58,25.01 26.58,23.21 26.99,22.8 29.53,22.8 30.42,21.91 32.57,21.91 33.97,20.51 36.77,20.51 38.29,22.04 38.29,32.33 39.18,33.21 39.18,37.91 v1(39.81,38.55) ; R53.1 v1(55.18,32.71)
  BOTTOM w0.127: v1(55.18,32.71) 54.67,33.21 50.25,33.21 50.24,33.23 v1(49.86,33.23) 49.85,33.21 49.24,33.21 44.91,37.54 40.82,37.54 v1(39.81,38.55)
MCU_LINK_SPI1_MISO: length 12.5
  TOP w0.102: 25.21,24.07 U8.G13
  TOP w0.127: R156.2 33.97,18.99 32.19,20.77 30.92,20.77 29.27,22.42 26.73,22.42 v1(25.8,23.35) 25.21,23.94 25.21,24.07
MCU_LINK_SPI1_MOSI: length 13
  TOP w0.102: U8.H12 v2(24.71,25.85)
  TOP w0.127: R154.2 33.97,19.88 32.57,21.28 31.43,21.28 v1(31.3,21.4)
  BOTTOM w0.102: v2(24.71,25.85) 25.21,25.85 26.48,24.58 26.99,24.58 27.49,24.07
  BOTTOM w0.127: 27.49,24.07 28.76,22.8 29.91,22.8 v1(31.3,21.4)
MCU_LINK_SPI1_SCLK: length 12.5
  TOP w0.127: v2(25.59,26.23) 25.59,25.76 U8.G12 ; v1(28.51,23.69) 29.65,23.69 30.67,22.67 33.59,22.67 34.23,22.04 R153.2
  BOTTOM w0.127: v1(28.51,23.69) 28.51,24.45 27.88,25.09 26.48,25.09 25.59,25.98 v2(25.59,26.23)
MCU_LINK_SPI1_SSEL: length 9.2
  TOP w0.127: v1(29.15,25.34) 32.7,25.34 33.97,24.07 R155.2 ; U8.B12 27.24,25.85 27.13,25.85 v2(27.11,25.87)
  BOTTOM w0.127: v2(27.11,25.87) 28.62,25.87 v1(29.15,25.34)
MCU_LINK_TX: length 6.3
  TOP w0.102: U8.A11 29.02,25.88
  TOP w0.127: 29.02,25.88 33.94,25.88 R216.2
MCU_RESET_B: length 146.2
  TOP w0.102: U1.F3 v2(60.69,28.52)
  TOP w0.127: R147.2 5.9,12.51 v1(6.09,12.32) 6.92,11.5 J12.10 ; R140.2 v1(36,34.74) 36.65,35.38 v1(36.65,38.55) ; D11.1 v1(12.83,11.75) 12.13,11.75 11.11,10.74 v1(10.48,10.74) ; v1(25.46,11.62) 25.46,8.83 27.24,7.05 27.24,4.51 J3.6 ; v1(18.48,46.17) 13.4,46.17 12.76,45.53 12.76,44.52 12.25,44.01 10.35,44.01 10.08,44.28 D12.C 9.27,44.9 9.21,44.83 R161.2 C87.1 C86.1 8.55,47.24 7.77,48.02 SW1.4 SW1.3
  BOTTOM w0.102: v2(60.69,28.52) 58.86,28.52
  BOTTOM w0.127: J3.6 27.49,3.37 26.35,4.51 21.4,4.51 17.21,8.7 14.67,8.7 12.83,10.54 v1(12.83,11.75) ; 58.86,28.52 56.6,28.52 52.4,32.72 49.35,32.72 44.78,37.29 37.91,37.29 v1(36.65,38.55) 35.51,38.55 27.89,46.17 v1(18.48,46.17) ; v1(6.09,12.32) 6.67,11.75 8.32,11.75 9.33,10.74 v1(10.48,10.74) ; v1(36,34.74) 36.77,33.98 36.77,23.84 29.4,16.47 29.4,13.15 27.87,11.62 v1(25.46,11.62)
MCU_UART_RX: length 45.2
  TOP w0.127: R216.1 36.51,25.47 37.02,25.98 37.02,32.96 37.91,33.85 37.91,39.31 v1(38.16,39.56) ; R54.1 v1(55.18,33.72) ; R56.1 47.69,26.74 46.93,27.5 46.93,30.55 47.81,31.44 47.81,31.94 49.1,33.23 49.1,33.86 v1(49.61,34.37)
  BOTTOM w0.127: v1(38.16,39.56) 40.32,39.56 42.09,37.8 45.04,37.8 48.47,34.37 v1(49.61,34.37) 50.25,33.72 v1(55.18,33.72)
MCU_USB1_DM: length 60.1
  TOP w0.13: L4.2 13.88,20.75 14.15,21.02 14.83,21.02 15.97,19.88 17.87,19.88 20.16,17.59 42.13,17.59 43.91,15.81 59.63,15.81 65.88,22.07 65.88,24.19 U1.R14
MCU_USB1_DP: length 59.5
  TOP w0.13: U1.R13 65.61,24.42 65.61,22.18 59.51,16.08 44.02,16.08 42.24,17.86 20.27,17.86 17.99,20.14 16.08,20.14 14.94,21.28 14.15,21.28 13.88,21.55 L4.3
MIC2_R: length 45.2
  TOP w0.102: U6.D16 98.94,29.15
  TOP w0.254: v1(99.25,17.21) 99.25,15.31 98.36,14.42 75.15,14.42 74.13,15.43 71.56,15.43 C61.2 ; v1(98.23,23.56) TP6.1 97.34,25.34 98.74,26.74 98.74,28.01 98.94,28.21 98.94,29.15
  BOTTOM w0.254: v1(99.25,17.21) 99.25,17.47 98.23,18.48 v1(98.23,23.56)
MIC_HDST: length 3.8
  TOP w0.254: R110.2 C61.1 R113.1 C54.1 L8.2
MICBIAS1: length 3.6
  TOP w0.102: U6.A15 100.27,29.56 100.27,29.16 100.65,28.77 101.09,28.77
  TOP w0.127: C50.1 101.16,28.77 101.09,28.77
MICBIAS2: length 46.9
  TOP w0.102: 99.96,28.95 U6.A17
  TOP w0.254: 99.96,28.95 100.65,28.26 v1(100.9,28.26) 101.36,27.8 C53.1 ; R110.1 71.18,14.93 73.88,14.93 74.77,14.04 98.74,14.04 99.88,15.18 99.88,17.59 v1(99.38,18.1)
  BOTTOM w0.254: v1(99.38,18.1) 98.87,18.61 98.87,21.15 100.01,22.29 100.01,27.37 v1(100.9,28.26)
P0_0/SWDIO: length 112.8
  TOP w0.102: U1.A17 67.94,31.5 68.52,32.07
  TOP w0.127: v1(39.19,41.99) 39.19,41.35 37.65,39.81 37.65,33.98 36.77,33.09 36.77,27.5 v1(36,26.74) R139.2 ; R145.2 2.86,12.77 v1(2.6,12.51) 1.84,11.75 J12.2 ; 68.52,32.07 69.79,33.34 70.93,33.34 71.96,34.37 71.96,37.67 v1(72.21,37.92) ; D11.6 v1(9.84,12.5)
  BOTTOM w0.127: v1(36,26.74) 35.11,25.85 35.11,23.05 28.89,16.83 28.89,13.4 27.88,12.39 17.84,12.39 15.94,14.29 12.38,14.29 10.59,12.5 v1(9.84,12.5) 9.35,12.5 8.44,13.4 4.89,13.4 4.13,12.64 4.13,12.26 3.87,12.01 3.11,12.01 v1(2.6,12.51) ; v1(72.21,37.92) 72.21,38.18 71.58,38.81 71.07,38.81 70.56,38.31 70.06,38.31 69.55,38.81 65.86,38.81 64.85,37.8 53.16,37.8 52.78,38.18 50.75,38.18 47.21,41.72 39.46,41.72 v1(39.19,41.99)
P0_1/SWCLK: length 111.5
  TOP w0.102: 68.26,32.33 67.75,31.82 67.51,31.82 U1.A16
  TOP w0.127: J12.4 3.11,12.13 v1(3.49,12.51) 3.87,12.89 R149.1 ; v1(43.51,41.23) 43.51,40.85 39.94,37.28 39.94,32.83 39.05,31.94 39.05,21.15 36.38,18.48 33.34,18.48 31.81,20.01 JP8.2 ; v1(71.33,38.31) 71.33,38.05 71.71,37.67 71.71,34.5 70.8,33.6 69.53,33.6 68.26,32.33 ; D11.5 9.97,13.15 v1(9.84,13.28)
  BOTTOM w0.127: v1(3.49,12.51) 4.63,13.66 8.7,13.66 9.08,13.28 v1(9.84,13.28) 11.24,14.67 15.94,14.67 17.97,12.64 27.75,12.64 28.64,13.53 28.64,17.09 29.78,18.23 JP8.2 ; v1(71.33,38.31) 71.07,38.05 69.8,38.05 69.29,38.56 65.99,38.56 64.98,37.54 53.01,37.54 52.63,37.92 50.62,37.92 47.58,40.97 43.77,40.97 v1(43.51,41.23)
P0_2/SWO: length 110.8
  TOP w0.102: U1.B16 66.89,31.3 66.89,31.59 67.63,32.33
  TOP w0.127: v1(38.43,41.99) 38.43,40.97 37.4,39.94 37.4,34.23 v1(36,32.83) R142.2 ; 67.63,32.33 67.94,32.64 69.15,33.85 70.67,33.85 71.33,34.5 71.33,36.27 v1(70.82,36.78) ; v1(9.84,11.75) 10.86,11.75 11.37,12.26 11.37,13.66 11.22,13.8 D11.4
  BOTTOM w0.127: v1(70.82,36.78) 52.5,36.78 52.13,37.15 50.1,37.15 49.33,37.92 48.34,37.92 45.56,40.71 42.86,40.71 42.1,41.47 38.95,41.47 v1(38.43,41.99) ; J12.6 4.38,11.5 4.51,11.62 4.51,12.51 5.14,13.15 8.06,13.15 9.46,11.75 v1(9.84,11.75) 10.35,11.75 12.51,13.91 15.94,13.91 17.72,12.13 28,12.13 29.15,13.28 29.15,16.58 36.51,23.94 36.51,32.33 v1(36,32.83)
P0_3/TDI: length 109.7
  TOP w0.102: 67.25,32.33 66.69,31.77 U1.B15
  TOP w0.127: J12.8 5.65,11.84 v1(5.12,12.37) 4.89,12.6 R146.2 ; R143.2 v1(36,35.63) 36,40.19 v1(37.67,41.86) ; v1(14.29,13.4) 13.89,13.8 D11.3 ; 67.25,32.33 68.21,33.29 69.02,34.1 69.79,34.1 70.82,35.13 v1(70.82,36.02)
  BOTTOM w0.127: v1(36,35.63) 37.02,34.61 37.02,23.56 29.65,16.2 29.65,13.02 27.75,11.12 18.35,11.12 16.06,13.4 v1(14.29,13.4) 14.16,13.53 12.64,13.53 10.35,11.24 9.46,11.24 7.81,12.89 5.65,12.89 v1(5.12,12.37) ; v1(37.67,41.86) 38.32,41.22 41.97,41.22 42.73,40.45 45.43,40.45 48.21,37.67 49.16,37.67 49.93,36.9 52.01,36.9 52.38,36.53 70.31,36.53 v1(70.82,36.02)
P0_4/SMARTDMA_CAMERA_VSYNC: length 32
  TOP w0.102: U1.B14 66.48,31.29 66.48,31.94 66.86,32.33
  TOP w0.127: v1(73.23,40.34) 72.6,40.34 70.31,38.05 70.31,35.13 69.54,34.36 68.9,34.36 68.48,33.94 66.86,32.33 ; J9.17 81.72,42.89 v1(83.14,41.48)
  BOTTOM w0.127: v1(73.23,40.34) 73.87,40.34 75.01,41.48 79.45,41.48 79.96,40.97 82.63,40.97 v1(83.14,41.48)
P0_5/SMARTDMA_CAMERA_HSYNC: length 5.1
  TOP w0.102: 66.48,32.33 66.23,32.07 66.23,31.54 U1.A14
  TOP w0.127: 66.48,32.33 67.39,33.23 67.39,33.99 v1(68.15,34.75)
  BOTTOM w0.127: v1(68.15,34.75) 67.86,34.46 SJ5.1
P0_6: length 108.8
  TOP w0.102: 66.1,32.33 65.98,32.2 65.98,31.82 65.85,31.69 65.85,30.84 U1.C14
  TOP w0.127: R2.1 v1(69.04,35.38) 68.15,35.38 67.13,34.37 67.13,33.36 66.1,32.33 ; R141.2 v1(36.51,21.02) 38.04,22.55 38.04,32.45 38.92,33.34 38.92,38.42 41.21,40.71 v1(41.85,40.71) ; D9.C v1(8.44,3.75) 8.44,4.13 5.65,6.92 J12.7
  BOTTOM w0.127: v1(8.44,3.75) 9.08,4.38 9.08,7.05 11.11,9.08 11.11,11.37 12.13,12.39 14.54,12.39 14.67,12.51 16.57,12.51 18.22,10.86 27.88,10.86 29.91,12.89 29.91,15.94 34.99,21.02 v1(36.51,21.02) ; v1(41.85,40.71) 42.35,40.2 45.3,40.2 48.09,37.42 49.05,37.42 49.82,36.64 51.78,36.64 52.15,36.27 68.15,36.27 v1(69.04,35.38)
P0_6/ISPMODE_N-SW: length 104.5
  TOP w0.127: R2.2 69.04,37.92 v1(68.91,38.05) ; v1(115.63,8.58) 115.51,8.45 C88.1 R162.2 106.11,7.59 106.57,7.12 SW3.3 SW3.4
  BOTTOM w0.127: v1(68.91,38.05) 68.91,37.92 69.04,37.8 71.58,37.8 72.34,37.04 88.6,37.04 89.22,37.66 92.52,37.66 93.03,38.17 93.03,39.31 93.92,40.2 96.46,40.2 100.27,44.01 107.76,44.01 109.03,45.28 114.24,45.28 116.01,43.51 116.01,8.95 v1(115.63,8.58)
P0_7/SMARTDMA_CAMERA_PCLK: length 16.3
  TOP w0.102: 65.72,32.33 65.72,31.94 65.59,31.82 65.59,30.59 U1.C13
  TOP w0.127: v1(72.47,42.24) 71.45,41.23 70.18,41.23 68.4,39.45 68.4,36.02 66.88,34.5 66.88,33.49 65.72,32.33
  BOTTOM w0.127: SJ4.1 72.21,41.99 v1(72.47,42.24)
P0_14/FXIO_D6: length 62.6
  TOP w0.102: U1.E11 65.19,29.5 v2(65.66,29.03)
  TOP w0.127: J8.15 111.57,27.5 109.66,27.5 108.01,29.15 108.01,36.54 106,38.56 v1(104.85,38.56)
  BOTTOM w0.102: 68.52,32.33 67.5,32.33 66.5,31.32 66.5,29.87 v2(65.66,29.03)
  BOTTOM w0.127: v1(104.85,38.56) 104.47,38.18 99.65,38.18 98.76,37.29 92.53,37.29 91.52,36.27 74.5,36.27 73.36,35.13 71.71,35.13 68.9,32.33 68.52,32.33
P0_15/FXIO_D7: length 59.8
  TOP w0.102: v2(65.22,28.51) 65.23,28.5 U1.G13
  TOP w0.127: J8.16 107.76,28.77 107.76,36.29 105.87,38.18 105.23,38.18 v1(104.85,37.8)
  BOTTOM w0.102: v2(65.22,28.51) 65.72,28.51 67.13,29.92 67.13,31.45 67.64,31.96 68.52,31.96
  BOTTOM w0.127: v1(104.85,37.8) 99.77,37.8 99.01,37.04 92.79,37.04 91.77,36.02 75.26,36.02 73.87,34.62 71.71,34.62 69.04,31.96 68.52,31.96
P0_16: length 47.6
  TOP w0.102: 65.47,32.33 65.47,32.28 U1.B10
  TOP w0.127: R160.1 36.51,33.85 37.15,34.48 37.15,40.58 v1(37.67,41.1) ; 65.47,32.33 65.47,32.45 66.63,33.61 66.63,35 v1(66.88,35.26) 67.13,35.26 67.88,36 R5.1
  BOTTOM w0.127: v1(37.67,41.1) 37.81,40.96 40.45,40.96 41.46,39.95 45.17,39.95 47.96,37.16 48.95,37.16 49.72,36.39 51.62,36.39 51.99,36.02 66.12,36.02 v1(66.88,35.26)
P0_16/PDM0_CLK-DMIC: length 114.5
  TOP w0.127: v1(51.5,17.21) 51.12,17.21 50.61,17.72 45.66,17.72 44.26,19.12 44.26,21.91 46.42,24.07 46.42,30.8 47.31,31.69 47.31,32.19 48.59,33.48 48.59,34.5 49.48,35.38 49.48,37.04 48.97,37.54 48.97,38.56 v1(48.34,39.19) ; U7.2 97.39,19.71 97.98,19.12 98.74,19.12 99.38,19.75 99.38,23.18 98.36,24.2 98.36,25.34 v1(98.74,25.72) 98.74,25.98 99.3,26.54 R96.1 ; v1(67.75,38.05) 67.88,37.92 R5.2 ; v1(93.66,28.39) 92.79,29.26 92.79,31.7 90.88,33.61 90.88,36.15 90.63,36.4 v1(90.63,36.78)
  BOTTOM w0.127: v1(98.74,25.72) 98.49,25.98 97.6,25.98 95.82,27.75 94.3,27.75 v1(93.66,28.39) ; J4.7 52.77,6.93 52.77,15.94 v1(51.5,17.21) ; v1(90.63,36.78) 90.01,37.41 89.35,37.41 88.73,36.78 72.09,36.78 71.33,37.54 68.26,37.54 v1(67.75,38.05) 65.99,38.05 65.23,37.29 52.88,37.29 52.51,37.66 50.38,37.66 48.97,39.07 48.47,39.07 v1(48.34,39.19)
P0_17: length 61.7
  TOP w0.102: U1.A10 64.19,31.56 64.96,32.33
  TOP w0.127: 64.96,32.33 66.37,33.74 66.37,35.9 R4.1 66.99,36.26 67.26,36.53 67.26,37.8 66.75,38.31 v1(66.75,41.48) ; R159.1 36.13,23.05 37.53,24.45 37.53,32.71 38.42,33.6 38.42,38.68 40.46,40.72 40.46,41.86 42.88,44.27 v1(43.13,44.27)
  BOTTOM w0.127: v1(43.13,44.27) 43.39,44.53 48.72,44.53 51.51,41.73 56.59,41.73 57.36,40.97 63.58,40.97 63.71,41.1 66.37,41.1 v1(66.75,41.48)
P0_17/PDM0_DATA0-DMIC: length 112.9
  TOP w0.127: v1(98.87,22.8) 98.61,22.8 97.39,21.57 U7.1 ; R99.1 v1(99.45,25.65) ; v1(94.42,28.39) 93.04,29.77 93.04,31.83 91.14,33.73 91.14,37.04 90.88,37.29 90.25,37.29 v1(89.74,36.78) ; v1(54.16,16.96) 53.91,16.7 51.12,16.7 50.35,17.47 45.55,17.47 44,19.01 44,22.02 46.16,24.18 46.16,30.93 47.05,31.82 47.05,32.32 48.34,33.61 48.34,34.62 49.23,35.51 49.23,36.78 48.47,37.54 v1(48.47,38.43) ; R4.2 v1(65.86,37.28)
  BOTTOM w0.127: J4.9 56.32,7.43 54.16,9.59 v1(54.16,16.96) ; v1(89.74,36.78) 89.49,36.53 71.83,36.53 71.08,37.28 v1(65.86,37.28) 65.73,37.28 65.48,37.04 52.63,37.04 52.26,37.41 50.23,37.41 49.45,38.18 48.72,38.18 v1(48.47,38.43) ; v1(98.87,22.8) 99.12,22.8 99.45,23.13 v1(99.45,25.65) 98.87,26.23 97.85,26.23 96.07,28.01 94.8,28.01 v1(94.42,28.39)
P0_18: length 63.8
  TOP w0.102: 64.58,32.33 63.89,31.64 63.89,30.8 U1.C10
  TOP w0.127: v1(50.1,16.96) 45.7,16.96 43.75,18.91 43.75,22.12 45.91,24.28 45.91,31.06 46.8,31.94 46.8,32.45 48.08,33.73 48.08,34.75 48.72,35.38 v1(48.72,36.65) ; v1(65.86,34.75) 65.86,33.61 64.58,32.33
  BOTTOM w0.127: J4.5 52.39,7.05 52.39,15.31 50.74,16.96 v1(50.1,16.96) ; v1(48.72,36.65) 48.82,36.65 49.34,36.14 51.37,36.14 51.74,35.77 64.85,35.77 v1(65.86,34.75) 65.9,34.71 SJ5.3
P0_19/GPIO: length 22.5
  TOP w0.102: U1.C9 63.69,31.82 64.2,32.33
  TOP w0.127: 64.2,32.33 64.85,32.98 64.85,38.31 65.48,38.94 65.48,46.18 64.98,46.69 64.98,50.6 J9.32
P0_20: length 96.6
  TOP w0.102: U1.C8 63.49,30.8 63.49,31.74 63.49,32 63.82,32.33
  TOP w0.127: J8.13 111.56,30.05 109.68,30.05 108.66,31.07 108.66,38.43 104.84,42.26 v1(104.84,44.52) R12.1 ; 63.82,32.33 64.59,33.1 64.59,38.43 65.23,39.07 65.23,46.03 62.69,48.57 62.69,51.26 61.93,52.02 v1(61.93,52.53)
  BOTTOM w0.127: v1(61.93,52.53) 62.18,52.53 63.58,53.93 102.29,53.93 103.82,52.39 103.82,45.53 v1(104.84,44.52)
P0_20/WUU0_IN4-SW: length 8.6
  TOP w0.127: SW2.3 SW2.4 106.57,47.23 v1(106.74,47.06) R164.2 C90.1 R12.2
P0_21: length 96.1
  TOP w0.102: U1.A8 63.19,32.07 63.32,32.21 63.32,32.33
  TOP w0.127: v1(62.18,48.85) 62.29,48.74 62.29,46.32 62.82,45.8 62.82,44.78 63.32,44.27 63.32,42.24 v1(63.52,42.05) 63.45,42.05 63.32,41.93 63.32,32.33 ; v1(80.6,41.48) 81.23,41.48 83.01,39.7 83.01,37.04 84.15,35.89 86.69,35.89 87.45,35.13 v1(87.45,35) 87.82,34.64 R13.1
  BOTTOM w0.127: J8.14 107.15,28.77 106.63,29.29 106.63,34.58 105.19,36.02 94.31,36.02 92.41,34.11 88.6,34.11 87.71,35 v1(87.45,35) ; v1(80.6,41.48) 80.09,41.48 79.83,41.73 74.88,41.73 73.99,40.85 69.93,40.85 68.28,42.5 66.25,42.5 65.74,41.99 63.71,41.99 63.64,42.05 v1(63.52,42.05) ; v1(62.18,48.85) 61.67,48.85 60.02,50.5 60.02,52.28 58.63,53.67 50.75,53.67 J1.10
P0_21/ACCL_INT1: length 4.5
  TOP w0.127: R173.2 85.03,31.06 U10.8 87.06,31.06 87.31,31.31 87.31,32.71 R13.2
P0_22: length 59.7
  TOP w0.102: 63.05,32.33 62.92,32.19 62.92,31.39 62.92,31.27 U1.B8
  TOP w0.127: 63.05,32.33 63.07,32.34 63.07,44.02 62.56,44.53 62.56,45.67 61.67,46.56 61.67,49.1 v1(62.18,49.61) ; J2.9 28.13,50.36 39.81,50.36 J1.16
  BOTTOM w0.127: J1.16 43.38,53.93 58.75,53.93 60.28,52.4 60.28,50.75 61.42,49.61 v1(62.18,49.61)
P0_23: length 104.7
  TOP w0.102: U1.B7 62.69,32.29 62.72,32.33
  TOP w0.127: v1(77.74,44.72) 77.74,43.07 80.22,40.59 81.61,40.59 82.76,39.45 82.76,36.78 84.03,35.51 86.06,35.51 v1(86.57,35) 86.8,34.77 R18.1 ; v1(61.93,45.42) 62.05,45.29 62.05,44.66 62.72,43.99 62.72,32.33
  BOTTOM w0.127: J8.5 111.57,37.66 108.53,37.66 107.14,36.27 94.19,36.27 92.28,34.37 88.85,34.37 87.71,35.51 87.07,35.51 v1(86.57,35) ; v1(77.74,44.72) 74.82,44.72 73.87,45.67 62.18,45.67 v1(61.93,45.42) 61.42,45.42 61.17,45.16 58.24,45.16 57.48,45.93 51.89,45.93 51.39,45.42 50.62,45.42 49.48,46.56 42.62,46.56 41.48,47.7 40.31,47.7 39.19,48.82 39.19,49.45 J2.2
P0_23/ACCL_WAKEUP: length 2.5
  TOP w0.127: R18.2 86.8,32.71 87.06,32.45 87.06,31.56 86.95,31.46 U10.7
P0_24: length 135.6
  TOP w0.102: 62.47,32.33 62.47,31.28 U1.B6
  TOP w0.127: 62.47,32.33 62.47,34.56 62.17,34.87 R14.1 61.78,36.9 61.66,37.02 61.66,38.16 62.18,38.69 62.18,40.58 61.42,41.34 61.42,49.48 62.44,50.5 62.44,51.13 v1(61.04,52.53) ; v1(107.65,44.53) 107.65,40.21 109.04,38.81 109.04,37.64 J8.8
  BOTTOM w0.127: v1(107.65,44.53) 104.22,47.96 104.22,52.53 102.57,54.18 62.69,54.18 v1(61.04,52.53) 60.53,52.53 58.88,54.18 19.26,54.18 17.99,52.91 17.99,50.38 J2.17
P0_24/ACCL_INT2: length 36
  TOP w0.127: U10.6 85.24,31.86 R174.2 85.03,32.59 84.9,32.72 83.52,32.72 80.47,35.77 80.47,39.7 79.45,40.72 77.29,40.72 v1(76.79,40.21) ; v1(62.18,41.48) 62.44,41.23 62.44,38.18 R14.2
  BOTTOM w0.127: v1(76.79,40.21) 76.15,39.58 72.72,39.58 71.96,40.34 69.67,40.34 68.03,41.98 66.62,41.98 65.99,41.35 62.31,41.35 v1(62.18,41.48)
P0_25/ADC0_B17-LIGHT_SENSOR: length 49.7
  TOP w0.102: 62.22,32.33 62.22,31.53 U1.A6
  TOP w0.127: R38.2 61.02,35.25 v1(61.98,34.29) 62.22,34.05 62.22,32.33
  BOTTOM w0.127: J2.11 26.22,47.18 27.37,47.18 34.48,40.07 40.19,40.07 42.22,38.05 45.16,38.05 48.35,34.87 50.61,34.87 50.98,34.5 61.77,34.5 v1(61.98,34.29)
P0_26/ADC0_B18-MC_VOLT_DCB: length 50.7
  TOP w0.102: U1.F10 63.79,29 v2(63.69,28.9)
  BOTTOM w0.102: 64.07,32.33 63.69,31.94 63.69,31.06 62.8,30.17 62.8,29.79 v2(63.69,28.9)
  BOTTOM w0.127: J2.7 29.4,45.66 34.73,40.33 40.32,40.33 41.33,39.32 44.02,39.32 44.67,38.68 45.3,38.68 48.6,35.37 50.86,35.37 51.23,35 64.21,35 64.72,34.5 64.72,32.98 64.07,32.33
P0_27/ADC0_B19-MC_BEMF_C: length 48.2
  TOP w0.102: v2(64.19,30.03) U1.E10
  BOTTOM w0.102: 64.83,32.33 64.19,31.68 v2(64.19,30.03)
  BOTTOM w0.127: J2.5 31.94,43.5 34.86,40.58 40.45,40.58 41.34,39.69 45.05,39.69 48.86,35.88 51.24,35.88 51.61,35.51 64.47,35.51 65.23,34.75 65.23,32.72 64.83,32.33
P0_28/ADC0_B20-MC_BEMF_B: length 48.6
  TOP w0.102: U1.E8 v2(63.69,29.5)
  TOP w0.127: v1(44.78,39.19) 46.69,41.1 v1(46.69,43)
  BOTTOM w0.102: 64.45,32.33 63.94,31.82 63.94,30.54 63.69,30.29 v2(63.69,29.5)
  BOTTOM w0.127: J2.3 34.48,48.1 37.8,44.78 39.19,44.78 40.85,43.13 42.12,43.13 42.75,42.5 46.18,42.5 v1(46.69,43) ; 64.45,32.33 64.98,32.85 64.98,34.62 64.34,35.26 51.39,35.26 51.02,35.63 48.73,35.63 45.17,39.18 44.79,39.18 v1(44.78,39.19)
P0_29/ADC0_B21-MC_BEMF_A: length 46.7
  TOP w0.102: U1.F8 v2(62.67,29)
  TOP w0.127: v1(45.93,43) 45.93,41.1 44.02,39.19 v1(44.02,38.56)
  BOTTOM w0.102: 63.69,32.33 63.44,32.07 63.44,31.18 62.6,30.34 62.6,29.08 v2(62.67,29)
  BOTTOM w0.127: 63.69,32.33 64.47,33.1 64.47,34.37 64.09,34.75 51.11,34.75 50.74,35.12 48.48,35.12 45.29,38.31 44.27,38.31 v1(44.02,38.56) ; J2.1 37.02,47.47 41.1,43.39 42.24,43.39 42.85,42.78 45.44,42.78 45.67,43 v1(45.93,43)
P1_0: length 117.6
  TOP w0.102: 61.96,32.33 61.96,32.25 61.93,32.22 61.93,32.21 61.91,32.19 61.91,30.8 62.19,30.52 U1.C6
  TOP w0.127: v1(92.66,11.64) 92.66,9.32 J7.3 ; v1(60.91,39.45) 60.91,38.81 60.51,38.42 60.51,37.02 60.39,36.9 R15.1 60.01,35.63 61.96,33.67 61.96,32.33 ; v1(44.78,43.64) 42.61,41.46 42.61,40.33 39.69,37.41 39.69,32.96 38.8,32.07 38.8,21.53 36.26,18.99 R156.1 ; v1(77.42,38.31) 77.93,37.8 77.93,37.29 82.25,32.97 v1(82.25,30.56)
  BOTTOM w0.127: v1(92.66,11.64) 91.76,12.54 J6.6 91.76,17.49 90.5,18.75 86.06,18.75 84.41,20.4 84.41,28.02 82.25,30.18 v1(82.25,30.56) ; v1(77.42,38.31) 73.23,38.31 71.71,39.83 65.1,39.83 64.09,38.81 61.55,38.81 v1(60.91,39.45) 60.66,39.7 56.72,39.7 56.34,40.08 53.93,40.08 53.04,40.97 50.5,40.97 47.45,44.02 45.16,44.02 v1(44.78,43.64)
P1_0/FC3_SPI_SDO-ARD_D11: length 5.3
  TOP w0.127: v1(60.01,38.68) R15.2
  BOTTOM w0.127: v1(60.01,38.68) 59.64,38.31 56.56,38.31 SJ2.1
P1_1: length 132.7
  TOP w0.102: U1.C5 61.69,32.21 61.68,32.22 61.68,32.33
  TOP w0.127: v1(90.12,11.64) 90.74,11.02 J7.7 ; v1(76.66,37.54) 76.66,37.29 81.23,32.72 v1(81.23,30.69) ; R153.1 36.26,22.04 37.78,23.56 37.78,32.58 38.67,33.47 38.67,38.55 41.73,41.61 v1(41.73,42.5) ; 61.68,32.33 61.68,33.57 59.37,35.88 59.37,38.83 v1(59.25,38.95)
  BOTTOM w0.127: J2.12 24.32,51.76 25.46,52.9 30.19,52.9 30.81,52.28 30.81,51.01 31.32,50.5 32.59,50.5 33.35,49.74 33.35,47.32 37.8,42.88 41.35,42.88 v1(41.73,42.5) 41.99,42.24 47.58,42.24 49.35,40.46 52.78,40.46 53.67,39.58 56.09,39.58 57.1,38.56 58.86,38.56 v1(59.25,38.95) 59.5,39.19 60.15,39.19 61.04,38.31 64.47,38.31 65.48,39.32 71.45,39.32 73.23,37.54 v1(76.66,37.54) ; v1(90.12,11.64) 86.68,15.08 J6.4 86.68,17.37 83.87,20.18 83.87,27.8 81.23,30.43 v1(81.23,30.69)
P1_2: length 139.4
  TOP w0.102: U1.C4 61.48,30.79 61.48,31.87 61.4,31.95 61.4,32.2 61.28,32.33
  TOP w0.127: v1(81.74,31.19) 81.74,32.97 77.38,37.33 77.38,37.51 v1(77.42,37.54) ; 61.28,32.33 60.02,33.58 60.02,34.72 58.63,36.12 58.63,38.94 v1(58.5,39.07) ; J2.10 25.72,50.49 25.72,48.33 26.34,47.7 41.73,47.7 44.02,45.42 v1(44.02,43.64) 44.02,43.39 42.35,41.72 42.35,40.45 39.43,37.53 39.43,33.09 38.54,32.2 38.54,21.78 36.64,19.88 R154.1 ; v1(91.01,11.64) 91.9,10.75 91.9,7.54 J7.5
  BOTTOM w0.127: v1(77.42,37.54) 76.91,38.05 73.1,38.05 71.58,39.58 65.36,39.58 64.34,38.56 61.17,38.56 60.28,39.45 58.88,39.45 v1(58.5,39.07) 56.97,39.07 56.21,39.83 53.8,39.83 52.91,40.72 50.24,40.72 47.32,43.64 45.54,43.64 45.04,43.13 44.53,43.13 v1(44.02,43.64) ; v1(81.74,31.19) 81.74,30.3 84.14,27.91 84.14,20.29 86.31,18.11 88.34,18.11 89.22,17.24 J6.5 89.22,14.32 91.01,12.52 v1(91.01,11.64)
P1_3: length 54.2
  TOP w0.102: 60.52,32.33 60.9,31.94 60.9,31.31 61.19,31.02 U1.B4
  TOP w0.127: v1(43.26,45.29) 43.26,45.16 40.08,41.99 40.08,40.72 38.16,38.8 38.16,33.72 37.27,32.83 37.27,25.09 36.26,24.07 R155.1 ; v1(57.99,41.73) 57.74,41.48 57.74,36.25 59.39,34.6 59.39,33.45 60.52,32.33
  BOTTOM w0.127: SJ1.1 58.12,41.86 v1(57.99,41.73) 57.48,42.24 51.77,42.24 48.97,45.04 43.39,45.04 43.26,45.16 v1(43.26,45.29)
P1_4/SMARTDMA_PIO0-CAMERA_D0: length 57.1
  TOP w0.102: 60.9,32.33 61.15,32.07 61.15,31.54 U1.A4
  TOP w0.127: v1(61.42,50.5) 61.17,50.24 61.17,43.89 57.99,40.72 57.99,36.37 59.77,34.6 59.77,33.45 60.9,32.33
  BOTTOM w0.127: v1(61.42,50.5) 61.42,51.26 61.73,51.57 62,51.57 63.85,53.42 92.63,53.42 J9.8
P1_5/SMARTDMA_PIO1-CAMERA_D1: length 53.6
  TOP w0.102: 60.16,32.33 60.69,31.79 U1.B3
  TOP w0.127: 60.16,32.33 59.13,33.35 59.13,34.37 57.48,36.02 57.48,41.86 60.02,44.4 v1(60.02,45.93)
  BOTTOM w0.127: J9.7 94.42,48.96 91.01,45.54 74.76,45.54 74.12,46.18 60.28,46.18 v1(60.02,45.93)
P1_6/SMARTDMA_PIO2-CAMERA_D2: length 55.4
  TOP w0.102: 59.75,32.33 60.48,31.6 60.48,31.29 U1.B2
  TOP w0.127: 59.75,32.33 58.86,33.22 58.86,34.23 57.21,35.88 57.21,41.97 59.51,44.27 59.51,46.56 60.91,47.96 60.91,50.75 61.17,51.01 v1(61.93,51.01)
  BOTTOM w0.127: J9.10 90.35,53.16 63.96,53.16 61.93,51.13 v1(61.93,51.01)
